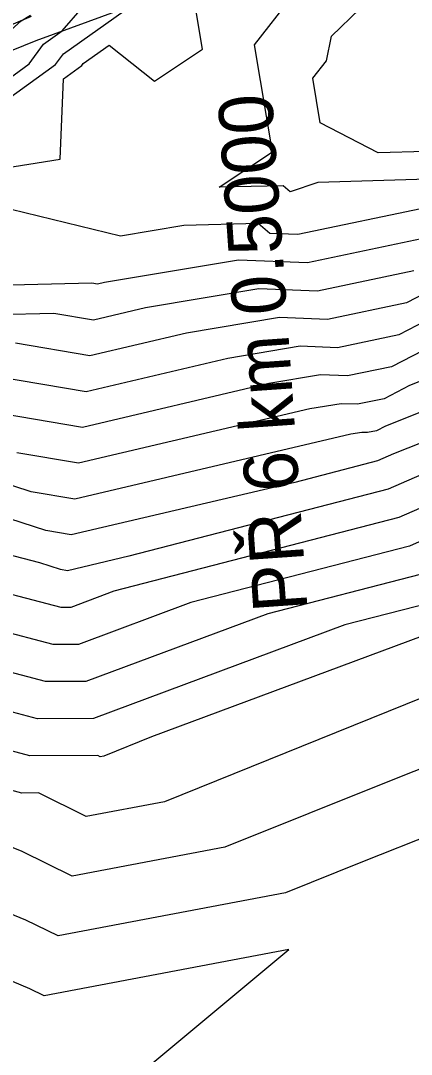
# Model space of a CAD drawing. Extents: x -549394 to -546608, y -1037055 to -1033629.
# Drawn here: x -547816.2 to -547750.8, y -1035710.4 to -1035537.3 of the extents above; entities that cross this region are included whole.
import ezdxf

# ---------------------------------------------------------------- set-up
doc = ezdxf.new("R2010")
doc.units = 0
for name, color, linetype in [('hlavni_vrst', 7, 'Continuous'), ('hrana_L', 7, 'Continuous'), ('norm_vrst', 7, 'Continuous'), ('x_popis_pricne_rezy_C1', 7, 'Continuous')]:
    doc.layers.add(name, color=color, linetype=linetype)

msp = doc.modelspace()

# ---------------------------------------------------------------- linework, layer by layer
at = {"layer": 'hlavni_vrst'}
for p, q in [((-547777.04, -1035541.33), (-547769.48, -1035531.68)), ((-547774.03, -1035559.28), (-547777.04, -1035541.33)), ((-547782.94, -1035565.21), (-547774.03, -1035559.28)), ((-547766.41, -1035564.39), (-547771.06, -1035565.95)), ((-547748.04, -1035563.85), (-547766.41, -1035564.39)), ((-547772.23, -1035564.94), (-547782.94, -1035565.21)), ((-547771.06, -1035565.95), (-547772.23, -1035564.94)), ((-547743.07, -1035584.83), (-547752.85, -1035589.91)), ((-547752.85, -1035589.91), (-547763.14, -1035592.07)), ((-547769.4, -1035591.83), (-547781.52, -1035593.85)), ((-547763.14, -1035592.07), (-547769.4, -1035591.83)), ((-547781.52, -1035593.85), (-547805.21, -1035599.43)), ((-547805.21, -1035599.43), (-547821.72, -1035596.64)), ((-547746.38, -1035612.11), (-547754.65, -1035615.77)), ((-547754.65, -1035615.77), (-547798.04, -1035626.99)), ((-547812.93, -1035628.1), (-547830.53, -1035623.58)), ((-547809.51, -1035629.21), (-547812.93, -1035628.1)), ((-547798.04, -1035626.99), (-547808.34, -1035629.41)), ((-547808.34, -1035629.41), (-547809.51, -1035629.21)), ((-547748.99, -1035640.35), (-547794.29, -1035657.24)), ((-547814.63, -1035660.41), (-547849.55, -1035651.2)), ((-547794.29, -1035657.24), (-547802.23, -1035660.44)), ((-547803.24, -1035660.37), (-547814.63, -1035660.41)), ((-547802.86, -1035660.56), (-547803.24, -1035660.37)), ((-547802.23, -1035660.44), (-547802.86, -1035660.56))]:
    msp.add_line(p, q, dxfattribs=at)
at = {"layer": 'hrana_L'}
for p, q in [((-547813.58, -1035540.62), (-547792.07, -1035532.74)), ((-547814.39, -1035536.61), (-547833.66, -1035544.82)), ((-547832.01, -1035548.06), (-547813.58, -1035540.62))]:
    msp.add_line(p, q, dxfattribs=at)
at = {"layer": 'norm_vrst'}
for p, q in [((-547809.01, -1035542.84), (-547797.48, -1035534.72)), ((-547816.07, -1035537.33), (-547814.54, -1035536.39)), ((-547809.23, -1035539.03), (-547805.82, -1035535.12)), ((-547785.74, -1035542.05), (-547786.8, -1035535.75)), ((-547764.16, -1035539.9), (-547759.4, -1035535.33)), ((-547821.64, -1035542.31), (-547816.07, -1035537.33)), ((-547812.35, -1035541.22), (-547809.23, -1035539.03)), ((-547765, -1035544.01), (-547764.16, -1035539.9)), ((-547814.73, -1035544.55), (-547812.35, -1035541.22)), ((-547805.68, -1035544.47), (-547801.37, -1035541.43)), ((-547801.37, -1035541.43), (-547793.79, -1035547.41)), ((-547810.32, -1035544.67), (-547809.01, -1035542.84)), ((-547793.79, -1035547.41), (-547785.74, -1035542.05)), ((-547821.28, -1035552.58), (-547810.32, -1035544.67)), ((-547818.92, -1035547.58), (-547814.73, -1035544.55)), ((-547809.01, -1035547.02), (-547805.91, -1035544.79)), ((-547805.91, -1035544.79), (-547805.68, -1035544.47)), ((-547767.28, -1035546.91), (-547765, -1035544.01)), ((-547809.54, -1035560.47), (-547809.01, -1035547.02)), ((-547766.02, -1035554.41), (-547767.28, -1035546.91)), ((-547756.31, -1035559.46), (-547766.02, -1035554.41)), ((-547748.34, -1035559.23), (-547756.31, -1035559.46)), ((-547824.52, -1035562.85), (-547809.54, -1035560.47)), ((-547799.43, -1035573.39), (-547821.16, -1035568.08)), ((-547747.85, -1035568.51), (-547769.8, -1035573.12)), ((-547776.43, -1035571.27), (-547788.87, -1035571.59)), ((-547774.49, -1035572.94), (-547776.43, -1035571.27)), ((-547788.87, -1035571.59), (-547799.43, -1035573.39)), ((-547769.8, -1035573.12), (-547774.49, -1035572.94)), ((-547749.1, -1035573.86), (-547768.14, -1035577.86)), ((-547779.72, -1035577.42), (-547802.13, -1035581.16)), ((-547768.14, -1035577.86), (-547779.72, -1035577.42)), ((-547739.05, -1035578.04), (-547751.6, -1035584.56)), ((-547750.35, -1035579.21), (-547766.47, -1035582.59)), ((-547804.25, -1035581.28), (-547834.2, -1035582)), ((-547803.33, -1035581.44), (-547804.25, -1035581.28)), ((-547802.13, -1035581.16), (-547803.33, -1035581.44)), ((-547776.28, -1035582.22), (-547795.26, -1035585.39)), ((-547766.47, -1035582.59), (-547776.28, -1035582.22)), ((-547751.6, -1035584.56), (-547764.81, -1035587.33)), ((-547810.63, -1035586.31), (-547829.92, -1035586.77)), ((-547803.96, -1035587.44), (-547810.63, -1035586.31)), ((-547795.26, -1035585.39), (-547803.96, -1035587.44)), ((-547772.84, -1035587.03), (-547788.39, -1035589.62)), ((-547764.81, -1035587.33), (-547772.84, -1035587.03)), ((-547788.39, -1035589.62), (-547804.58, -1035593.43)), ((-547804.58, -1035593.43), (-547817.01, -1035591.33)), ((-547747.09, -1035591.62), (-547754.1, -1035595.26)), ((-547732.46, -1035591.01), (-547751.11, -1035598.41)), ((-547754.1, -1035595.26), (-547761.47, -1035596.8)), ((-547765.96, -1035596.63), (-547774.64, -1035598.08)), ((-547761.47, -1035596.8), (-547765.96, -1035596.63)), ((-547732.14, -1035596.08), (-547755.13, -1035605.19)), ((-547774.64, -1035598.08), (-547805.84, -1035605.43)), ((-547751.11, -1035598.41), (-547755.35, -1035600.61)), ((-547755.35, -1035600.61), (-547759.81, -1035601.54)), ((-547767.77, -1035602.32), (-547806.46, -1035611.42)), ((-547762.52, -1035601.44), (-547767.77, -1035602.32)), ((-547759.81, -1035601.54), (-547762.52, -1035601.44)), ((-547731.82, -1035601.14), (-547753.78, -1035609.85)), ((-547805.84, -1035605.43), (-547819.27, -1035603.15)), ((-547756.6, -1035605.96), (-547758.14, -1035606.28)), ((-547755.13, -1035605.19), (-547756.6, -1035605.96)), ((-547760.9, -1035606.55), (-547807.09, -1035617.42)), ((-547759.08, -1035606.24), (-547760.9, -1035606.55)), ((-547758.14, -1035606.28), (-547759.08, -1035606.24)), ((-547806.46, -1035611.42), (-547816.83, -1035609.67)), ((-547756.42, -1035611.02), (-547770.3, -1035614.61)), ((-547753.78, -1035609.85), (-547756.42, -1035611.02)), ((-547814.39, -1035616.18), (-547824.89, -1035612.77)), ((-547770.3, -1035614.61), (-547807.72, -1035623.41)), ((-547738.98, -1035614.37), (-547752.87, -1035620.52)), ((-547807.09, -1035617.42), (-547814.39, -1035616.18)), ((-547731.58, -1035616.62), (-547751.1, -1035625.27)), ((-547811.95, -1035622.7), (-547824.38, -1035618.66)), ((-547752.87, -1035620.52), (-547800.58, -1035632.85)), ((-547807.72, -1035623.41), (-547811.95, -1035622.7)), ((-547751.1, -1035625.27), (-547787.68, -1035634.73)), ((-547814.08, -1035634.31), (-547834.93, -1035628.95)), ((-547749.32, -1035630.02), (-547774.79, -1035636.6)), ((-547800.58, -1035632.85), (-547807.79, -1035635.54)), ((-547809.39, -1035635.54), (-547814.08, -1035634.31)), ((-547787.68, -1035634.73), (-547806.51, -1035641.75)), ((-547747.54, -1035634.76), (-547761.89, -1035638.47)), ((-547807.79, -1035635.54), (-547809.39, -1035635.54)), ((-547774.79, -1035636.6), (-547805.23, -1035647.95)), ((-547810.7, -1035641.76), (-547822.95, -1035638.53)), ((-547761.89, -1035638.47), (-547803.95, -1035654.16)), ((-547806.51, -1035641.75), (-547810.7, -1035641.76)), ((-547812.01, -1035647.98), (-547831.81, -1035642.75)), ((-547813.32, -1035654.2), (-547840.68, -1035646.98)), ((-547805.23, -1035647.95), (-547812.01, -1035647.98)), ((-547748.84, -1035650.65), (-547792.11, -1035668.08)), ((-547803.95, -1035654.16), (-547813.32, -1035654.2)), ((-547739.01, -1035658.48), (-547753.9, -1035664.41)), ((-547815.94, -1035666.63), (-547835.62, -1035661.44)), ((-547753.9, -1035664.41), (-547781.99, -1035675.72)), ((-547813.18, -1035666.62), (-547815.94, -1035666.63)), ((-547805.2, -1035670.56), (-547813.18, -1035666.62)), ((-547792.11, -1035668.08), (-547805.2, -1035670.56)), ((-547735.36, -1035668.77), (-547758.96, -1035678.16)), ((-547815.92, -1035676.43), (-547824.21, -1035673.02)), ((-547807.54, -1035680.57), (-547815.92, -1035676.43)), ((-547781.99, -1035675.72), (-547807.54, -1035680.57)), ((-547758.96, -1035678.16), (-547771.86, -1035683.36)), ((-547815.27, -1035687.91), (-547835.75, -1035679.5)), ((-547771.86, -1035683.36), (-547809.88, -1035690.57)), ((-547814.62, -1035699.39), (-547847.29, -1035685.97)), ((-547809.88, -1035690.57), (-547815.27, -1035687.91)), ((-547771.29, -1035692.81), (-547812.23, -1035700.58)), ((-547797.3, -1035714.51), (-547771.29, -1035692.81)), ((-547812.23, -1035700.58), (-547814.62, -1035699.39))]:
    msp.add_line(p, q, dxfattribs=at)

# ---------------------------------------------------------------- texts
at = {"layer": 'x_popis_pricne_rezy_C1'}
msp.add_text('PŘ 6 km 0.5000', height=9.0627, rotation=93.972, dxfattribs=at).set_placement((-547768.14, -1035636))

doc.saveas('drawing.dxf')
